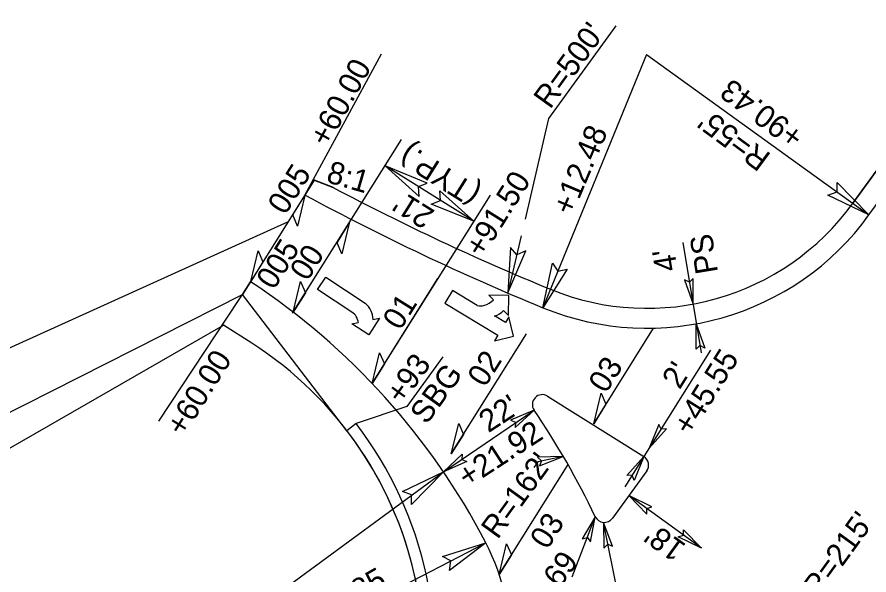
# Model space of a CAD drawing. Extents: x 1183930 to 1185370, y 573068 to 574871.
# Drawn here: x 1184226.2 to 1184397.2, y 573816.9 to 573929 of the extents above; entities that cross this region are included whole.
import ezdxf

# ---------------------------------------------------------------- set-up
doc = ezdxf.new("R2010")
doc.units = 0
for name, color, linetype in [('E_NCDOT_Terrain_Model_Breakline', 7, 'Continuous'), ('E_NCDOT_Terrain_Model_Contour_Minor', 7, 'Continuous'), ('E_NCDOT_Terrain_Model_Points_High', 7, 'Continuous'), ('E_NCDOT_Terrain_Model_Triangles', 7, 'Continuous'), ('E_NCDOT_Vertical_Profile_Ground_Line', 7, 'Continuous'), ('P_NCDOT_Horizontal_Alignment', 7, 'Continuous'), ('P_NCDOT_Horizontal_Alignment_Tick_Large', 7, 'Continuous'), ('PC_BEAM', 7, 'Continuous'), ('PC_COLUMN', 7, 'Continuous'), ('PC_OBJECT', 7, 'Continuous'), ('PC_PADFOOTING', 7, 'Continuous'), ('PC_SLAB', 7, 'Continuous'), ('PS_HATCH', 7, 'Continuous')]:
    doc.layers.add(name, color=color, linetype=linetype)

msp = doc.modelspace()

# ---------------------------------------------------------------- linework, layer by layer
for points in [[(1184308.54, 573895.61), (1184300.09, 573899.08), (1184306.91, 573892.92), (1184306.78, 573894.89)], [(1184311.09, 573894.01), (1184317.89, 573887.92), (1184309.37, 573891.37), (1184311.2, 573892.12)], [(1184325.26, 573882.64), (1184324.71, 573873.52), (1184328.33, 573881.97), (1184326.51, 573881.21)], [(1184360.22, 573876.14), (1184361.91, 573871.29), (1184361.96, 573876.46), (1184361.18, 573875.67)], [(1184362.53, 573862.2), (1184362.56, 573867.34), (1184364.28, 573862.46), (1184363.29, 573862.95)], [(1184326.23, 573846.48), (1184330, 573849.97), (1184325.24, 573847.95), (1184326.28, 573847.55)], [(1184355.07, 573847.12), (1184353.12, 573842.36), (1184356.58, 573846.2), (1184355.48, 573846.13)], [(1184316.52, 573839.65), (1184311.8, 573837.62), (1184315.57, 573841.15), (1184315.52, 573840.04)], [(1184348.63, 573836.84), (1184352.06, 573840.67), (1184350.11, 573835.88), (1184349.7, 573836.9)], [(1184353.62, 573830.56), (1184349.01, 573832.82), (1184352.6, 573829.1), (1184352.61, 573830.21)], [(1184360, 573825.94), (1184363.59, 573822.26), (1184358.94, 573824.52), (1184359.99, 573824.87)]]:
    msp.add_lwpolyline(points, close=True)
at = {"layer": 'E_NCDOT_Terrain_Model_Breakline'}
for p, q in [((1184332.72, 573852.79), (1184352.06, 573840.67)), ((1184352.61, 573837.8), (1184345.71, 573828.26))]:
    msp.add_line(p, q, dxfattribs=at)
for centre, radius, start, end in [((1184331.65, 573851.1), 2, 57.9152, 214.2169), ((1184196.04, 573758.88), 162, 25.4808, 34.2169), ((1184350.99, 573838.97), 2, 324.103, 57.9152), ((1184344.09, 573829.43), 2, 205.4808, 324.103)]:
    msp.add_arc(centre, radius, start, end, dxfattribs=at)
at = {"layer": 'E_NCDOT_Terrain_Model_Contour_Minor'}
for p, q in [((1184352.59, 573921.42), (1184331.77, 573870.56)), ((1184352.59, 573921.42), (1184397.22, 573889.19)), ((1184330.78, 573839.61), (1184329.93, 573838.43)), ((1184335.86, 573840.69), (1184330.78, 573839.61)), ((1184280.82, 573814.8), (1184311.8, 573837.62)), ((1184337.65, 573816.49), (1184342.28, 573828.57)), ((1184347.97, 573807.36), (1184343.91, 573827.44)), ((1184282.14, 573803.55), (1184320.31, 573823.35))]:
    msp.add_line(p, q, dxfattribs=at)
for points in [[(1184390.83, 573895.72), (1184397.22, 573889.19), (1184388.94, 573893.19), (1184390.81, 573893.82)], [(1184336.62, 573878.3), (1184331.77, 573870.56), (1184333.72, 573879.54), (1184334.76, 573877.87)], [(1184331.09, 573838.78), (1184335.86, 573840.69), (1184330.69, 573840.51), (1184331.52, 573839.77)], [(1184303.59, 573833.61), (1184311.8, 573837.62), (1184305.4, 573831.02), (1184305.39, 573832.99)], [(1184341.29, 573823.53), (1184342.28, 573828.57), (1184339.62, 573824.14), (1184340.69, 573824.42)], [(1184341.29, 573823.53), (1184342.28, 573828.57), (1184339.62, 573824.14), (1184340.69, 573824.42)], [(1184345.76, 573822.65), (1184343.91, 573827.44), (1184344.03, 573822.27), (1184344.79, 573823.08)], [(1184311.61, 573820.58), (1184320.31, 573823.35), (1184313.02, 573817.76), (1184313.3, 573819.71)]]:
    msp.add_lwpolyline(points, close=True, dxfattribs=at)
at = {"layer": 'E_NCDOT_Terrain_Model_Points_High'}
for p, q in [((1184332.72, 573852.79), (1184352.06, 573840.67)), ((1184352.61, 573837.8), (1184345.71, 573828.26))]:
    msp.add_line(p, q, dxfattribs=at)
for centre, radius, start, end in [((1184331.65, 573851.1), 2, 57.9152, 214.2169), ((1184196.04, 573758.88), 162, 25.4808, 34.2169), ((1184350.99, 573838.97), 2, 324.103, 57.9152), ((1184344.09, 573829.43), 2, 205.4808, 324.103)]:
    msp.add_arc(centre, radius, start, end, dxfattribs=at)
at = {"layer": 'E_NCDOT_Terrain_Model_Triangles'}
msp.add_arc((1184232.86, 573800.29), 77.33, 347.1573, 37.4184, dxfattribs=at)
at = {"layer": 'E_NCDOT_Vertical_Profile_Ground_Line'}
for p, q in [((1184393.98, 573891.54), (1184409.04, 573912.35)), ((1184393.98, 573891.54), (1184409.04, 573912.35)), ((1184285.88, 573896.17), (1184289.68, 573894.7)), ((1184285.88, 573896.17), (1184289.68, 573894.7)), ((1184292.43, 573845.86), (1184271.5, 573873.22)), ((1184292.43, 573845.86), (1184271.5, 573873.22))]:
    msp.add_line(p, q, dxfattribs=at)
for centre, radius, start, end in [((1184521.69, 574333.09), 496, 242.1114, 247.677), ((1184521.69, 574333.09), 496, 242.1114, 247.677), ((1184352.66, 573921.44), 51, 247.677, 324.103), ((1184352.66, 573921.44), 51, 247.677, 324.103), ((1184232.86, 573800.29), 75, 324.0683, 37.4184)]:
    msp.add_arc(centre, radius, start, end, dxfattribs=at)
at = {"layer": 'P_NCDOT_Horizontal_Alignment'}
msp.add_line((1184285.88, 573896.17), (1184271.5, 573873.22), dxfattribs=at)
for centre, radius, start, end in [((1184521.69, 574333.09), 500, 241.6183, 247.677), ((1184352.66, 573921.44), 55, 247.677, 324.103), ((1184196.04, 573758.88), 140, 27.4188, 56.6074), ((1184282.14, 573803.55), 43, 324.0929, 27.4188)]:
    msp.add_arc(centre, radius, start, end, dxfattribs=at)
at = {"layer": 'P_NCDOT_Horizontal_Alignment_Tick_Large'}
msp.add_line((1184273.35, 573863.42), (1184267.65, 573867.08), dxfattribs=at)
msp.add_arc((1184232.86, 573800.29), 75, 324.0683, 57.3255, dxfattribs=at)
at = {"layer": 'PC_BEAM'}
for p, q in [((1184286.54, 573874.22), (1184288.18, 573876.69)), ((1184288.18, 573876.69), (1184296.1, 573871.45)), ((1184293.41, 573869.67), (1184286.54, 573874.22)), ((1184313.64, 573874), (1184312.1, 573871.46)), ((1184318.6, 573871), (1184313.64, 573874)), ((1184324.92, 573873.01), (1184320.93, 573873.11)), ((1184320.93, 573873.11), (1184321.83, 573872.15)), ((1184324.83, 573869.02), (1184324.92, 573873.01)), ((1184312.1, 573871.46), (1184322.73, 573865.03)), ((1184324.26, 573867.57), (1184322.07, 573868.9)), ((1184323.89, 573870.01), (1184324.83, 573869.02)), ((1184324.96, 573868.73), (1184324.26, 573867.57)), ((1184325.88, 573864.86), (1184324.96, 573868.73)), ((1184293.41, 573867.3), (1184294.72, 573867.57)), ((1184296.81, 573865.1), (1184293.41, 573867.3)), ((1184298.96, 573868.43), (1184296.81, 573865.1)), ((1184297.65, 573868.16), (1184298.96, 573868.43)), ((1184322.73, 573865.03), (1184322.03, 573863.88)), ((1184322.03, 573863.88), (1184325.88, 573864.86))]:
    msp.add_line(p, q, dxfattribs=at)
for centre, radius, start, end in [((1184318.9, 573874.87), 3.99, 286.2862, 317.1397), ((1184292.94, 573867.96), 4.73, 2.5284, 47.8401), ((1184319.25, 573873.18), 2.27, 253.4643, 289.7762), ((1184291.8, 573867.22), 2.95, 6.858, 56.5162), ((1184320.96, 573872.72), 3.99, 286.3799, 317.2585)]:
    msp.add_arc(centre, radius, start, end, dxfattribs=at)
at = {"layer": 'PC_COLUMN'}
for points in [[(1184284, 573893.11), (1184282.5, 573886.97), (1184281.54, 573889.2)], [(1184292.89, 573887.54), (1184291.4, 573881.39), (1184290.44, 573883.62)], [(1184273.11, 573875.84), (1184274.6, 573881.99), (1184275.57, 573879.76)], [(1184281.65, 573869.65), (1184283.14, 573875.8), (1184284.11, 573873.57)], [(1184297.48, 573855.36), (1184298.97, 573861.51), (1184299.94, 573859.28)], [(1184341.97, 573847.26), (1184343.46, 573853.41), (1184344.43, 573851.18)], [(1184313.37, 573841.18), (1184314.87, 573847.33), (1184315.83, 573845.1)], [(1184322.99, 573816.98), (1184324.48, 573823.13), (1184325.45, 573820.9)]]:
    msp.add_lwpolyline(points, close=True, dxfattribs=at)
at = {"layer": 'PC_OBJECT'}
for p, q in [((1184397.22, 573889.19), (1184480.88, 574004.78)), ((1184409.04, 573912.35), (1184393.98, 573891.54)), ((1184285.88, 573896.17), (1184284.01, 573893.19))]:
    msp.add_line(p, q, dxfattribs=at)
for points in [[(1184289.68, 573894.7), (1184289.68, 573894.7)], [(1184294.28, 573847.28), (1184292.43, 573845.86), (1184271.5, 573873.22), (1184273.09, 573875.77)]]:
    msp.add_lwpolyline(points, dxfattribs=at)
for centre, radius, start, end in [((1184521.69, 574333.09), 496, 242.1114, 247.677), ((1184521.69, 574333.09), 500, 241.6183, 247.677), ((1184352.66, 573921.44), 51, 247.677, 324.1029), ((1184352.66, 573921.44), 55, 247.677, 324.103), ((1184196.04, 573758.88), 140, 27.4188, 56.6074), ((1184232.86, 573800.29), 77.33, 347.1573, 37.4184), ((1184282.14, 573803.55), 43, 324.0929, 27.4188)]:
    msp.add_arc(centre, radius, start, end, dxfattribs=at)
for points in [[(1184287.15, 573895.68), (1184287.11, 573895.69), (1184287.06, 573895.71), (1184287.01, 573895.73), (1184286.96, 573895.75), (1184286.91, 573895.77), (1184286.86, 573895.79), (1184286.8, 573895.81), (1184286.75, 573895.83), (1184286.7, 573895.85), (1184286.65, 573895.87), (1184286.6, 573895.89), (1184286.55, 573895.91), (1184286.5, 573895.93), (1184286.44, 573895.95), (1184286.39, 573895.97), (1184286.34, 573895.99), (1184286.29, 573896.01), (1184286.24, 573896.03), (1184286.19, 573896.05), (1184286.14, 573896.07), (1184286.09, 573896.09), (1184286.03, 573896.11), (1184285.98, 573896.13), (1184285.93, 573896.15), (1184285.88, 573896.17)], [(1184288.41, 573895.19), (1184288.4, 573895.19), (1184288.34, 573895.21), (1184288.29, 573895.23), (1184288.24, 573895.25), (1184288.19, 573895.27), (1184288.14, 573895.29), (1184288.09, 573895.31), (1184288.04, 573895.33), (1184287.99, 573895.35), (1184287.93, 573895.37), (1184287.88, 573895.39), (1184287.83, 573895.41), (1184287.78, 573895.43), (1184287.73, 573895.45), (1184287.68, 573895.47), (1184287.63, 573895.49), (1184287.57, 573895.51), (1184287.52, 573895.53), (1184287.47, 573895.55), (1184287.42, 573895.57), (1184287.37, 573895.59), (1184287.32, 573895.61), (1184287.27, 573895.63), (1184287.22, 573895.65), (1184287.16, 573895.67), (1184287.15, 573895.68)], [(1184289.68, 573894.7), (1184289.58, 573894.74), (1184289.53, 573894.76), (1184289.47, 573894.78), (1184289.42, 573894.8), (1184289.37, 573894.82), (1184289.32, 573894.84), (1184289.27, 573894.86), (1184289.22, 573894.87), (1184289.17, 573894.89), (1184289.12, 573894.91), (1184289.06, 573894.93), (1184289.01, 573894.95), (1184288.96, 573894.97), (1184288.91, 573894.99), (1184288.86, 573895.01), (1184288.81, 573895.03), (1184288.76, 573895.05), (1184288.7, 573895.07), (1184288.65, 573895.09), (1184288.6, 573895.11), (1184288.55, 573895.13), (1184288.5, 573895.15), (1184288.45, 573895.17), (1184288.41, 573895.19)]]:
    msp.add_spline(points, degree=3, dxfattribs=at)
at = {"layer": 'PC_PADFOOTING'}
for p, q in [((1184346.39, 573927.21), (1184332.92, 573908.6)), ((1184284.01, 573893.19), (1184299.34, 573921.56)), ((1184332.92, 573908.6), (1184328.18, 573888.34)), ((1184281.53, 573869.46), (1184303.4, 573904.34)), ((1184317.89, 573887.92), (1184300.1, 573899.08)), ((1184321.19, 573893.19), (1184297.46, 573855.34)), ((1184327.4, 573884.98), (1184324.71, 573873.52)), ((1184359.86, 573883.64), (1184363.53, 573861.48)), ((1184273.09, 573875.77), (1184254.63, 573847.75)), ((1184078.72, 573775.62), (1184271.5, 573873.22)), ((1184091.98, 573766.03), (1184267.65, 573867.08)), ((1184365.43, 573862.01), (1184348.24, 573834.58)), ((1184311.69, 573860.71), (1184304.48, 573850.69)), ((1184304.48, 573850.69), (1184294.28, 573847.28)), ((1184311.81, 573837.6), (1184330, 573849.97)), ((1184363.59, 573822.26), (1184349.01, 573832.82))]:
    msp.add_line(p, q, dxfattribs=at)
at = {"layer": 'PC_SLAB'}
for p, q in [((1184281.65, 573869.65), (1184292.91, 573887.61)), ((1184297.48, 573855.36), (1184310.7, 573876.46)), ((1184313.37, 573841.18), (1184328.5, 573865.3)), ((1184341.97, 573847.26), (1184354, 573866.46)), ((1184322.99, 573816.98), (1184336.82, 573839.04))]:
    msp.add_line(p, q, dxfattribs=at)
at = {"layer": 'PS_HATCH'}
msp.add_line((1184280.64, 573887.8), (1184061.17, 573788.33), dxfattribs=at)

# ---------------------------------------------------------------- texts
at = {"layer": 'E_NCDOT_Terrain_Model_Contour_Minor'}
for s, rotation, p in [('+90.43', 143.5927, (1184384.53, 573905.74)), ("R=55'", 143.5927, (1184377.78, 573901.31)), ('+12.48', 67.0176, (1184337.61, 573888.87)), ("R=162'", 54.103, (1184322.68, 573823.86)), ("R=215'", 54.103, (1184387.19, 573811.99)), ('+43.69', 54.103, (1184328.18, 573804.47)), ('+27.85', 29.5265, (1184284.59, 573805.54))]:
    msp.add_text(s, height=4.5, rotation=rotation, dxfattribs=at).set_placement(p)
at = {"layer": 'PC_PADFOOTING'}
for s, rotation, p in [("R=500'", 54.103, (1184333.22, 573910.28)), ('+60.00', 61.3937, (1184288.56, 573902.62)), ('(TYP.)', 147.9152, (1184319.61, 573894.46)), ('8:1', 343.851, (1184288.08, 573895.85)), ('+91.50', 57.9152, (1184319.61, 573880.39)), ("21'", 147.9152, (1184310.29, 573889.95)), ('PS', 99.4265, (1184366.94, 573877.72)), ("4'", 99.4265, (1184358.82, 573878.19)), ('+60.00', 57.9152, (1184259.62, 573844.46)), ('+45.55', 57.9152, (1184361.39, 573844.62)), ('+93', 54.2438, (1184303.51, 573850.93)), ("2'", 57.9152, (1184359.21, 573853.97)), ('SBG', 54.2438, (1184308.43, 573846.92)), ("22'", 33.0594, (1184320.83, 573845.33)), ('+21.92', 33.0594, (1184316.59, 573834.27)), ("18'", 144.103, (1184360.74, 573822.87))]:
    msp.add_text(s, height=4.5, rotation=rotation, dxfattribs=at).set_placement(p)
at = {"layer": 'PC_SLAB'}
for s, p in [('005', (1184280.06, 573889)), ('005', (1184277.76, 573873.95)), ('00', (1184284.5, 573875.7)), ('01', (1184303.13, 573865.82)), ('02', (1184320.15, 573854.39)), ('03', (1184344.44, 573853.17)), ('03', (1184332.69, 573821.79))]:
    msp.add_text(s, height=4.5, rotation=57.9152, dxfattribs=at).set_placement(p)

doc.saveas('drawing.dxf')
